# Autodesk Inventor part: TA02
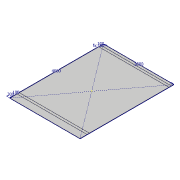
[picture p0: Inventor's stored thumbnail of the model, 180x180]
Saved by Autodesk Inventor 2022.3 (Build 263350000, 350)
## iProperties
Created: 2023-09
Part Number: TA02
Material: Generico
Document SubType Name: Modeling
Designer: Michela.Gerbotto
Density: 1 g/cm^3
Appearance: Default
Author: Michela.Gerbotto
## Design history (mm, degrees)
sketch "Schizzo1"
  geometry: L1 (-1500, 2000)-(1500, 2000); L2 (1500, 2000)-(1500, -2000); L3 (1500, -2000)-(-1500, -2000); L4 (-1500, -2000)-(-1500, 2000); L5 (-1500, 2000)-(1500, -2000); L6 (1500, 2000)-(-1500, -2000); L7 (-1500, 1700)-(1500, 1700); L8 (1500, 1700)-(1500, 1600); L9 (1500, 1600)-(-1500, 1600); L10 (-1500, 1600)-(-1500, 1700); L11 (1500, -1800)-(1500, -1900); L12 (1500, -1900)-(-1500, -1900); L13 (-1500, -1900)-(-1500, -1800); L14 (-1500, -1800)-(1500, -1800); 5 further points
  constraints: 28 end point, 6 parallel, 5 point on line, 4 perpendicular, 2 midpoint, 1 horizontal
  dimensions: "d0" = 3000 distance of L2.end L3.end; "d1" = 4000 distance of L1.end L2.end; "d2" = 100 distance of L7.end L8.end; "d3" = 100 distance between parallel lines of L12 L14 (= d2); "d4" = 100 distance between parallel lines of L3 L12; "d5" = 300 distance between parallel lines of L7 L1
extrude "Estrusione1" new body sketch "Schizzo1" distance "d6" = 5; taper "d7" = 0 deg
extrude "Estrusione2" new body sketch "Schizzo1" distance "d8" = 5; taper "d9" = 0 deg
fillet "Raccordo1" dims "d10" = 2
fillet "Raccordo2" dims "d11" = 2
node "Solido1"
node "Solido2"
